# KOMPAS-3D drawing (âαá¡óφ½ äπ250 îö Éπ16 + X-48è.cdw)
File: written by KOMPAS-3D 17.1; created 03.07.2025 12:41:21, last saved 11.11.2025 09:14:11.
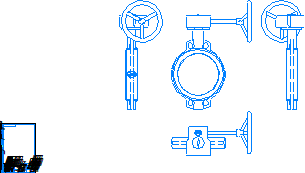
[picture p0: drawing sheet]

Sheet 1: A4, portrait

Title block, sheet 1: name: Гранвэл Ду250 МФ Ру16 + / X-48К (Габаритный / чертёж); material: Сталь 20  ГОСТ 1050-88; mass: 30,41; sheets: 1; sheet format: A4; stored path: \\adlc.lan\data\АДЛ_ПКД\3D-модели\ADL production\Дисковые поворотные затворы ГРАНВЭЛ\межфланцевый с китайским редуктором Ру16\KOMPAS 2D\Гранвэл Ду250 МФ Ру16 + X-48К.cdw

Views: Вид 1, Спереди, Проекционный вид 2, Проекционный вид 3, Проекционный вид 4
Referenced files in \\adlc.lan\data\АДЛ_ПКД\3D-модели\ADL production\Дисковые поворотные затворы ГРАНВЭЛ\межфланцевый с китайским редуктором Ру16\KOMPAS 3D\: Гранвэл Ду250 МФ Ру16 + X-48К.m3d
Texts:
  Andrey
  АДЛ
Dimensions and other numbers on the sheet: 1:1; 1; 30,41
